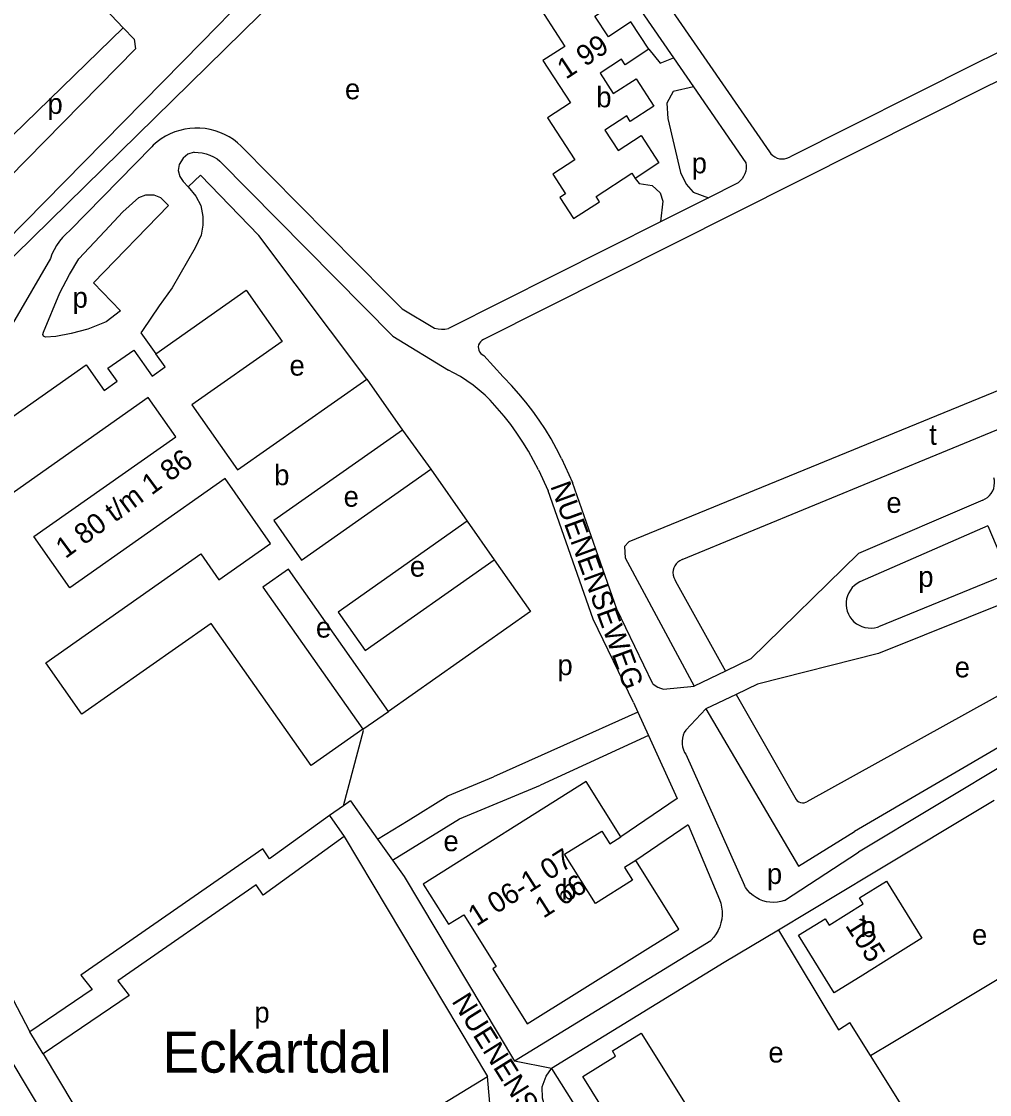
# Model space of a CAD drawing. Extents: x 161773 to 163836, y 384796 to 386521.
# Drawn here: x 163048.5 to 163236.9, y 386170.2 to 386379 of the extents above; entities that cross this region are included whole.
import ezdxf

# ---------------------------------------------------------------- set-up
doc = ezdxf.new("R2010")
doc.units = 0
for name, color, linetype in [('BLT_Basislijn', 7, 'Continuous'), ('BLT_Bebouwing', 7, 'Continuous'), ('BLT_Centroide', 7, 'Continuous'), ('BLT_Huisnummer', 7, 'Continuous'), ('BLT_Huisnummer_reeks', 7, 'Continuous'), ('BLT_Straatnaam_verkleind', 7, 'Continuous'), ('BLT_Terrein_beschrifting', 7, 'Continuous'), ('BLT_Vlakafsluiter', 7, 'Continuous')]:
    doc.layers.add(name, color=color, linetype=linetype)

msp = doc.modelspace()

# ---------------------------------------------------------------- linework, layer by layer
at = {"layer": 'BLT_Basislijn'}
for p, q in [((163037.35, 386323.86), (163137.51, 386422.15)), ((163129.84, 386422.38), (163083.65, 386374.98)), ((163164.92, 386395.95), (163194.09, 386353.62)), ((163160.8, 386393.11), (163175.41, 386371.92)), ((163068.33, 386377.77), (163064.8, 386381.46)), ((163254.94, 386380.98), (163234.23, 386370.81)), ((163255.93, 386375.9), (163236.43, 386366.33)), ((163175.41, 386371.92), (163179.29, 386366.29)), ((163234.23, 386370.81), (163198.1, 386352.65)), ((163236.43, 386366.33), (163138.46, 386317.08)), ((163179.29, 386366.29), (163189.47, 386351.51)), ((163073.89, 386354.62), (163057.95, 386338.31)), ((163087.16, 386351.81), (163120.83, 386317.74)), ((163080.99, 386346.81), (163083.4, 386349.07)), ((163187.75, 386347.45), (163182.22, 386344.67)), ((163182.22, 386344.67), (163172.88, 386339.98)), ((163172.88, 386339.98), (163131.66, 386319.26)), ((163054.15, 386332.88), (163044.73, 386316.57)), ((163277.62, 386323.2), (163166.7, 386277.73)), ((163071.74, 386318.42), (163074.69, 386314.34)), ((163120.83, 386317.74), (163131.65, 386311.13)), ((163138.53, 386314.03), (163142.29, 386309.82)), ((163177.09, 386274.27), (163273.81, 386314.14)), ((163122.71, 386299.49), (163128.17, 386291.85)), ((163153.64, 386293.93), (163155.74, 386289.31)), ((163149.14, 386291.74), (163151.02, 386287.66)), ((163235.6, 386285.85), (163211.43, 386275.48)), ((163135.28, 386281.74), (163140.5, 386274.24)), ((163236.61, 386280.84), (163211.69, 386269.92)), ((163236.61, 386280.84), (163240.56, 386271.52)), ((163211.43, 386275.48), (163190.5, 386254.96)), ((163289.93, 386276.27), (163201.36, 386227.16)), ((163297.18, 386271.92), (163210.65, 386221.36)), ((163240.56, 386271.52), (163215.31, 386261.22)), ((163175.82, 386270.1), (163185.52, 386252.58)), ((163300.51, 386270.98), (163211.4, 386217.34)), ((163242.87, 386267.06), (163215.34, 386256)), ((163190.5, 386254.96), (163185.52, 386252.58)), ((163215.34, 386256), (163191.74, 386250.01)), ((163185.52, 386252.58), (163179.47, 386249.68)), ((163173.47, 386249.08), (163179.47, 386249.68)), ((163191.74, 386250.01), (163187.64, 386248.05)), ((163167.61, 386246.45), (163168.46, 386244.6)), ((163187.64, 386248.05), (163181.71, 386245.21)), ((163187.64, 386248.05), (163199.28, 386227.57)), ((163114.94, 386241.27), (163119.97, 386244.72)), ((163168.46, 386244.6), (163154.02, 386238.12)), ((163168.46, 386244.6), (163170.53, 386240.05)), ((163181.71, 386245.21), (163177.82, 386241.11)), ((163170.53, 386240.05), (163149.52, 386230.4)), ((163170.53, 386240.05), (163176.14, 386227.78)), ((163154.02, 386238.12), (163140.39, 386232.01)), ((163177.82, 386236.4), (163189.23, 386210.85)), ((163112.55, 386227.35), (163111.17, 386226.38)), ((163112.55, 386227.35), (163115.49, 386223.19)), ((163176.14, 386227.78), (163165.2, 386220.3)), ((163237.86, 386227.43), (163213.97, 386213.05)), ((163111.17, 386226.38), (163108.47, 386224.46)), ((163108.47, 386224.46), (163111.36, 386220.38)), ((163115.49, 386223.19), (163117.84, 386219.89)), ((163117.84, 386219.89), (163123.76, 386223.53)), ((163178.3, 386222.69), (163168.08, 386215.71)), ((163178.3, 386222.69), (163184.39, 386208.15)), ((163111.36, 386220.38), (163139.24, 386173.7)), ((163117.84, 386219.89), (163120.73, 386215.8)), ((163197.02, 386207.95), (163211.4, 386217.34)), ((163120.73, 386215.8), (163122.99, 386212.61)), ((163122.99, 386212.61), (163144.46, 386176.65)), ((163213.97, 386213.05), (163195.86, 386202.19)), ((163195.86, 386202.19), (163185.28, 386195.85)), ((163218.08, 386180.34), (163254.97, 386202.51)), ((163182.67, 386200.11), (163144.46, 386176.65)), ((163185.28, 386195.85), (163151.7, 386175.22)), ((163045.97, 386190.34), (163050.17, 386182.37)), ((163213.79, 386177.76), (163209.76, 386184.21)), ((163052.74, 386178.07), (163050.17, 386182.37)), ((163213.79, 386177.76), (163218.08, 386180.34)), ((163221.36, 386165.67), (163213.79, 386177.76))]:
    msp.add_line(p, q, dxfattribs=at)
for points in [[(163037.23, 386347.61), (163068.33, 386377.77)], [(163068.33, 386377.77), (163070.43, 386375.56), (163070.7, 386373.7), (163042.45, 386344.93), (163039.99, 386344.77), (163037.23, 386347.61)], [(163033.14, 386324), (163037.67, 386328.35), (163083.65, 386374.98)], [(163170.62, 386373.59), (163172.85, 386370.86), (163175.41, 386371.92)], [(163179.29, 386366.29), (163175.33, 386365.39), (163174.15, 386363.08), (163174.33, 386360.14), (163176.79, 386349.62), (163177.91, 386347.33), (163179.25, 386345.8), (163182.22, 386344.67)], [(163091.31, 386354.74), (163090.57, 386355.4), (163089.78, 386356.01), (163088.94, 386356.55), (163088.06, 386357.02), (163087.15, 386357.41), (163086.21, 386357.74), (163085.25, 386357.98), (163084.27, 386358.15), (163083.27, 386358.24), (163082.28, 386358.25), (163081.29, 386358.18), (163080.3, 386358.03), (163079.33, 386357.8), (163078.39, 386357.5), (163077.47, 386357.12), (163076.58, 386356.67), (163075.73, 386356.14), (163074.93, 386355.56), (163074.18, 386354.9), (163073.89, 386354.62)], [(163091.31, 386354.74), (163119.52, 386326.17), (163122.6, 386323.09), (163128.94, 386319.29)], [(163082.13, 386353.54), (163080.88, 386353.21), (163079.99, 386352.43), (163079.19, 386351.15), (163079.05, 386350.02), (163079.34, 386348.81), (163079.98, 386347.83), (163080.99, 386346.81)], [(163082.13, 386353.54), (163082.91, 386353.52), (163083.69, 386353.42), (163084.45, 386353.24), (163085.19, 386352.98), (163085.9, 386352.65), (163086.58, 386352.24), (163087.16, 386351.81)], [(163194.09, 386353.62), (163194.38, 386353.24), (163194.74, 386352.9), (163195.15, 386352.63), (163195.59, 386352.43), (163196.06, 386352.3), (163196.55, 386352.25), (163197.04, 386352.28), (163197.51, 386352.39), (163197.97, 386352.58), (163198.1, 386352.65)], [(163189.47, 386351.51), (163189.55, 386350.96), (163189.55, 386350.41), (163189.47, 386349.86), (163189.31, 386349.34), (163189.07, 386348.84), (163188.77, 386348.37), (163188.4, 386347.96), (163187.98, 386347.61), (163187.75, 386347.45)], [(163115.74, 386309.4), (163094.75, 386337.32), (163083.4, 386349.07)], [(163167.97, 386348.46), (163168.71, 386347.49), (163171.26, 386347.08), (163172.8, 386345.66), (163173.37, 386344.05), (163172.88, 386339.98)], [(163080.99, 386346.81), (163082.49, 386345.01), (163083.43, 386343.21), (163083.85, 386341.08), (163083.81, 386339.36), (163083.48, 386337.44), (163082.35, 386334.94), (163077.88, 386327.14), (163075.33, 386323.65), (163072.11, 386318.85), (163071.74, 386318.42)], [(163057.95, 386338.31), (163057.22, 386337.67), (163056.54, 386336.98), (163055.92, 386336.23), (163055.37, 386335.43), (163054.88, 386334.59), (163054.46, 386333.71), (163054.15, 386332.88)], [(163128.94, 386319.29), (163129.6, 386319.16), (163130.27, 386319.11), (163130.94, 386319.13), (163131.66, 386319.26)], [(163138.46, 386317.08), (163138.14, 386316.91), (163137.87, 386316.68), (163137.65, 386316.39), (163137.5, 386316.07), (163137.43, 386315.71), (163137.44, 386315.35), (163137.52, 386315.01), (163137.68, 386314.68), (163137.91, 386314.41), (163138.2, 386314.19), (163138.53, 386314.03)], [(163138.76, 386306.28), (163137.63, 386307.28), (163136.44, 386308.22), (163135.21, 386309.1), (163133.94, 386309.9), (163132.62, 386310.65), (163131.65, 386311.13)], [(163153.64, 386293.93), (163152.66, 386295.86), (163151.6, 386297.75), (163150.48, 386299.6), (163149.29, 386301.41), (163148.03, 386303.18), (163146.71, 386304.9), (163145.32, 386306.56), (163143.88, 386308.18), (163142.37, 386309.74), (163142.29, 386309.82)], [(163149.14, 386291.74), (163148.2, 386293.58), (163147.19, 386295.39), (163146.11, 386297.16), (163144.96, 386298.88), (163143.74, 386300.56), (163142.46, 386302.19), (163141.12, 386303.77), (163139.72, 386305.3), (163138.76, 386306.28)], [(163235.6, 386285.85), (163236.09, 386286.08), (163236.54, 386286.38), (163236.93, 386286.75), (163237.27, 386287.17), (163237.54, 386287.63), (163237.74, 386288.13), (163237.86, 386288.65), (163237.91, 386289.19), (163237.87, 386289.72), (163237.77, 386290.22)], [(163171.39, 386250.12), (163164.39, 386264.62), (163155.74, 386289.31)], [(163167.61, 386246.45), (163159.76, 386262.7), (163151.02, 386287.66)], [(163166.7, 386277.73), (163165.86, 386276.81), (163166.04, 386274.63), (163179.47, 386249.68)], [(163177.09, 386274.27), (163176.67, 386274.07), (163176.29, 386273.8), (163175.96, 386273.47), (163175.69, 386273.08), (163175.49, 386272.66), (163175.36, 386272.21), (163175.31, 386271.74), (163175.35, 386271.27), (163175.46, 386270.82), (163175.65, 386270.39), (163175.82, 386270.1)], [(163211.69, 386269.92), (163211.15, 386269.62), (163210.66, 386269.25), (163210.22, 386268.83), (163209.84, 386268.34), (163209.52, 386267.82), (163209.28, 386267.25), (163209.11, 386266.66), (163209.02, 386266.06), (163209.01, 386265.44), (163209.08, 386264.83), (163209.23, 386264.24), (163209.45, 386263.66), (163209.75, 386263.13), (163210.11, 386262.63), (163210.54, 386262.19), (163211.02, 386261.8), (163211.54, 386261.49), (163212.1, 386261.24), (163212.69, 386261.06), (163213.3, 386260.97), (163213.91, 386260.95), (163214.52, 386261.02), (163215.12, 386261.16), (163215.31, 386261.22)], [(163171.39, 386250.12), (163171.85, 386249.75), (163172.36, 386249.46), (163172.9, 386249.23), (163173.47, 386249.08)], [(163181.71, 386245.21), (163199.73, 386214.65), (163210.65, 386221.36)], [(163111.17, 386226.38), (163115.11, 386241.02), (163114.94, 386241.27)], [(163177.82, 386241.11), (163177.52, 386240.62), (163177.3, 386240.09), (163177.15, 386239.54), (163177.08, 386238.97), (163177.09, 386238.39), (163177.18, 386237.83), (163177.35, 386237.28), (163177.59, 386236.76), (163177.82, 386236.4)], [(163123.76, 386223.53), (163131.49, 386228.3), (163140.39, 386232.01)], [(163120.73, 386215.8), (163133.78, 386223.83), (163149.52, 386230.4)], [(163199.28, 386227.57), (163199.52, 386227.31), (163199.82, 386227.11), (163200.15, 386226.98), (163200.5, 386226.93), (163200.85, 386226.96), (163201.19, 386227.07), (163201.36, 386227.16)], [(163108.47, 386224.46), (163096.82, 386216.05), (163095.53, 386217.96)], [(163111.36, 386220.38), (163095.56, 386208.97), (163094.21, 386210.97)], [(163095.53, 386217.96), (163060.1, 386193.42), (163062.27, 386190.6), (163050.17, 386182.37)], [(163094.21, 386210.97), (163067.27, 386192.31), (163069.46, 386189.45), (163052.74, 386178.07)], [(163197.02, 386207.95), (163196.33, 386207.74), (163195.63, 386207.61), (163194.91, 386207.56), (163194.2, 386207.59), (163193.49, 386207.7), (163192.8, 386207.89), (163192.14, 386208.15), (163191.5, 386208.49), (163190.91, 386208.89), (163190.37, 386209.36), (163189.89, 386209.88), (163189.46, 386210.46), (163189.23, 386210.85)], [(163184.39, 386208.15), (163184.63, 386207.41), (163184.79, 386206.65), (163184.88, 386205.88), (163184.88, 386205.1), (163184.8, 386204.33), (163184.65, 386203.57), (163184.41, 386202.82), (163184.11, 386202.11), (163183.73, 386201.43), (163183.28, 386200.8), (163182.77, 386200.21), (163182.67, 386200.11)], [(163195.86, 386202.19), (163207.54, 386182.76), (163209.76, 386184.21)], [(163040.95, 386187.06), (163045.12, 386179.13), (163069.09, 386139.03), (163071.07, 386136.57), (163073.23, 386134.36), (163076.43, 386132.53), (163079.69, 386132.23), (163082.33, 386132.46), (163084.57, 386133.32), (163139.8, 386167.01)], [(163052.74, 386178.07), (163074.03, 386142.47), (163075.57, 386140.56), (163076.94, 386139.15), (163078.27, 386138.39), (163079.71, 386138.26), (163080.98, 386138.36), (163081.91, 386138.72), (163139.24, 386173.7)], [(163162.8, 386148.23), (163150.45, 386167.65), (163149.95, 386169.44), (163149.87, 386171.68), (163150.62, 386173.76), (163151.7, 386175.22)], [(163151.7, 386175.22), (163162.48, 386158.05)]]:
    msp.add_lwpolyline(points, dxfattribs=at)
msp.add_lwpolyline([(163077.16, 386343.2), (163062.52, 386328.12), (163067.77, 386322.71), (163064.99, 386320.53), (163061.44, 386319.12), (163058.19, 386318.26), (163055.19, 386317.71), (163053.23, 386317.58), (163052.83, 386317.74), (163052.69, 386318.07), (163052.82, 386318.54), (163055.99, 386326.22), (163057.85, 386329.75), (163059.67, 386332.83), (163064.75, 386338.21), (163068.27, 386341.94), (163071.37, 386344.76), (163072.73, 386345.29), (163074.29, 386345.27), (163075.61, 386344.74)], close=True, dxfattribs=at)
at = {"layer": 'BLT_Bebouwing'}
for p, q in [((163115.74, 386309.4), (163122.71, 386299.49)), ((163128.17, 386291.85), (163135.28, 386281.74)), ((163158.44, 386231.12), (163126.72, 386211.09)), ((163165.2, 386220.3), (163158.44, 386231.12)), ((163176.43, 386202.34), (163168.08, 386215.71)), ((163218.07, 386197.04), (163212.24, 386193.42)), ((163163.53, 386178.65), (163169.11, 386182.15)), ((163169.11, 386182.15), (163178.03, 386167.92)), ((163157.78, 386173.71), (163164.14, 386177.67)), ((163164.14, 386177.67), (163163.53, 386178.65)), ((163163.46, 386164.63), (163157.78, 386173.71))]:
    msp.add_line(p, q, dxfattribs=at)
for points in [[(163170.62, 386373.59), (163167.13, 386378.92), (163162.75, 386376.04), (163160.11, 386380.03), (163161.21, 386380.74), (163158.39, 386385.03), (163156.04, 386388.64), (163148.22, 386383.52), (163154.3, 386374.16), (163150.02, 386371.39), (163155.38, 386363.14), (163150.89, 386360.23), (163156.19, 386352.07), (163151.91, 386349.29), (163154.42, 386345.44), (163153.32, 386344.72), (163155.97, 386340.63), (163161.02, 386343.91), (163160.34, 386344.96), (163167.31, 386349.49), (163167.97, 386348.46)], [(163170.62, 386373.59), (163166.01, 386370.57), (163165.33, 386371.66), (163161.12, 386368.93), (163163.7, 386364.96), (163168.14, 386367.86), (163171.6, 386362.53), (163166.98, 386359.52), (163166.31, 386360.63), (163162.07, 386357.88), (163164.66, 386353.89), (163169.1, 386356.82), (163172.57, 386351.51), (163167.97, 386348.46)], [(163074.69, 386314.34), (163092.24, 386326.68), (163099.25, 386316.72), (163081.7, 386304.38), (163090.6, 386291.73), (163115.74, 386309.4)], [(163039.99, 386297.33), (163061.12, 386312.19), (163064.62, 386307.21), (163067.13, 386308.98), (163065.35, 386311.52), (163070.38, 386315.06), (163073.94, 386310), (163076.48, 386311.79), (163074.69, 386314.34)], [(163114.94, 386241.27), (163104.89, 386234.2), (163085.44, 386261.86), (163060.3, 386244.18), (163053.27, 386254.18), (163083.42, 386275.38), (163086.95, 386270.36), (163097.02, 386277.43), (163088.16, 386290.03), (163057.96, 386268.8), (163050.96, 386278.76), (163078.57, 386298.18), (163073.21, 386305.81), (163040.51, 386282.81), (163033.5, 386292.77), (163039.99, 386297.33)], [(163122.71, 386299.49), (163097.64, 386281.86), (163103.04, 386274.18), (163128.17, 386291.85)], [(163135.28, 386281.74), (163110.14, 386264.05), (163115.39, 386256.58), (163140.5, 386274.24)], [(163140.5, 386274.24), (163147.6, 386264.15), (163119.97, 386244.72)], [(163119.97, 386244.72), (163100.49, 386272.42), (163095.5, 386268.91), (163114.94, 386241.27)], [(163168.08, 386215.71), (163165.89, 386214.34), (163167.43, 386211.87), (163160.22, 386207.37), (163154.24, 386216.94), (163161.46, 386221.45), (163163.02, 386218.95), (163165.2, 386220.3)], [(163126.72, 386211.09), (163131.63, 386203.3), (163134.6, 386205.17), (163140.94, 386195.11), (163140.23, 386194.67), (163146.92, 386183.91), (163176.43, 386202.34)], [(163212.24, 386193.42), (163206.71, 386189.99), (163199.77, 386201.18), (163204.94, 386204.39), (163205.71, 386203.14), (163212.34, 386207.26), (163211.6, 386208.44), (163216.87, 386211.71)], [(163216.87, 386211.71), (163223.77, 386200.58), (163218.07, 386197.04)]]:
    msp.add_lwpolyline(points, dxfattribs=at)
at = {"layer": 'BLT_Vlakafsluiter'}
for p, q in [((163151.7, 386175.22), (163144.46, 386176.65)), ((163139.8, 386167.01), (163139.24, 386173.7))]:
    msp.add_line(p, q, dxfattribs=at)

# ---------------------------------------------------------------- texts
at = {"layer": 'BLT_Centroide'}
for s, p in [('e', (163111.48, 386363.86)), ('b', (163160.39, 386362.3)), ('p', (163053.59, 386361.01)), ('p', (163178.96, 386349.45)), ('p', (163058.47, 386323.29)), ('e', (163100.69, 386310.08)), ('t', (163225.2, 386296.62)), ('b', (163097.71, 386288.76)), ('e', (163111.22, 386284.57)), ('e', (163216.85, 386283.37)), ('e', (163124.11, 386270.96)), ('p', (163223.06, 386268.97)), ('e', (163105.83, 386259.1)), ('p', (163152.84, 386251.78)), ('e', (163230.15, 386251.36)), ('e', (163130.65, 386217.53)), ('p', (163193.6, 386211.15)), ('b', (163153.61, 386208.11)), ('b', (163211.79, 386200.84)), ('e', (163233.51, 386199.3)), ('p', (163093.85, 386184.19)), ('e', (163193.88, 386176.41))]:
    msp.add_text(s, height=4, dxfattribs=at).set_placement(p)
at = {"layer": 'BLT_Huisnummer'}
for s, rotation, p in [('1 99', 33.522, (163154.49, 386367.64)), ('105', 302.3296, (163208.74, 386203.09))]:
    msp.add_text(s, height=4, rotation=rotation, dxfattribs=at).set_placement(p)
at = {"layer": 'BLT_Huisnummer_reeks'}
for s, rotation, p in [('1 80 t/m 1 86', 36.4024, (163057.08, 386274.35)), ('1 06-1 07', 32.4804, (163137.09, 386202.81)), ('1 66', 32.479, (163150.09, 386204.37))]:
    msp.add_text(s, height=4, rotation=rotation, dxfattribs=at).set_placement(p)
at = {"layer": 'BLT_Straatnaam_verkleind'}
for rotation, p in [(290.0755, (163151.4, 386288.6)), (302.0755, (163132.16, 386188.33))]:
    msp.add_text('NUENENSEWEG', height=4, rotation=rotation, dxfattribs=at).set_placement(p)
at = {"layer": 'BLT_Terrein_beschrifting'}
msp.add_text('Eckartdal', height=8, dxfattribs=at).set_placement((163075.97, 386174.43))

doc.saveas('drawing.dxf')
